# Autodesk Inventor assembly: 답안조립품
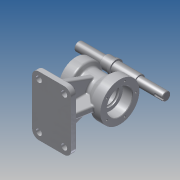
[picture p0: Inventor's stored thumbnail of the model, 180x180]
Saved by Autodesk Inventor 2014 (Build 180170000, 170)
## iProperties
Created: 2015-08
Part Number: 답안조립품
Document SubType Name: Assembly
Designer: SDA20
Author: SDA20
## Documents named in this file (3)
- C:\Users\SDA20\Desktop\450805v1015\답안조립품.iam
- C:\Users\SDA20\Desktop\450805v1015\본체.ipt
- C:\Users\SDA20\Desktop\450805v1015\축.ipt
